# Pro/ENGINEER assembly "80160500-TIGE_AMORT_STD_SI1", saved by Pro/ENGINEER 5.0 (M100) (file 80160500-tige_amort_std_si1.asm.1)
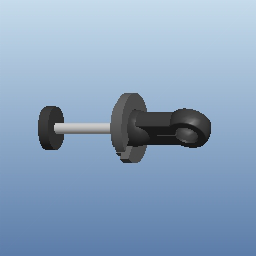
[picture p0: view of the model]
Units: millimeter Newton Second (mmNs); MM, TONNE, HOURS

Other components: 80160500-TIGE_AMORT_STD_SI1, 80160500-COUPELLE_AMORT_STD_SI1

Other named items: 80160500-TIGE_AMORT_STD_01, 80160500-COUPELLE_AMORT_STD_01, A-DROITE, A-DESSUS, A-FACE, A-R0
